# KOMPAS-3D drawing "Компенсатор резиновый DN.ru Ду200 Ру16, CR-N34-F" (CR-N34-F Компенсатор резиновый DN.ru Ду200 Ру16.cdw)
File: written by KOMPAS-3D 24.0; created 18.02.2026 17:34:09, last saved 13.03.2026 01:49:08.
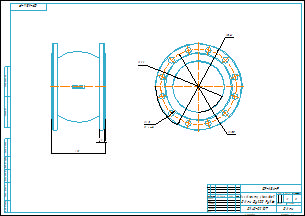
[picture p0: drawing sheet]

Document properties: Типовые: Типовые; Автор: DN.RU; Форматы листов документа: A2; Полное имя файла: CR-N34-F Компенсатор резиновый DN.ru Ду200 Ру16.m3d; Масса: 20; Наименование: Компенсатор резиновый DN.ru Ду200 Ру16; Количество листов документа: 1; Комментарий: D140--02107; Примечание: D140-02107

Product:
- Body: Твердое тело2  | qty 1
    Масса: 46.753709
- Part/product: Компенсатор резиновый DN.ru Ду200 Ру16  | designation CR-N34-F
    Масса: 20
    Раздел спецификации: Прочие изделия
    Форматы листов документа: A2
    Комментарий: D140--02107
    Примечание: D140-02107
    additional columns: Типовые

Views: Вид 1, Спереди, Проекционный вид 2
Referenced files in E:\Работа\Зайцев\CR-N34-F Компенсатор резиновый DN.ru ДУ25-300 Ру10-16\DN200_PN16\: CR-N34-F Компенсатор резиновый DN.ru Ду200 Ру16.m3d
Referenced files in E:\Работа\Зайцев\Для компаса\: чертеж DN.ru А3.cdt
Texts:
  CR-N34-F
  чертеж DN.ru А3.cdt
  Компенсатор резиновый
  DN.ru Ду200 Ру16
  Твердое тело2
  Компенсатор резиновый DN.ru Ду200 Ру16
  CR-N34-F Компенсатор резиновый DN.ru Ду200 Ру16
Dimensions and other numbers on the sheet: 0; 3; 2; 4; 210; 20; 340; 295; 200; 23; 12 отв.; 1:2; 1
